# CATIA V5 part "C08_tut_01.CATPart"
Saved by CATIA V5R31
Part number: Part1
Bounding box of the stored display mesh (mm): x -175 to 175, y -250 to 250, z -8 to 100
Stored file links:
  D:\PROJECTS\Project 2021\US EDITION\CATIA V5 6R 2021\Resources\Tutorial Files\c08_catia_v5_6r2021_tut\C08_tut_01.CATPart
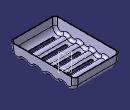
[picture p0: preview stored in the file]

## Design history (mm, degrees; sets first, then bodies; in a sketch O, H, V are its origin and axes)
Body1 (main body)
  Sketch1 on yz-plane, origin (0, 0, 0), H (0, 1, 0), V (0, 0, 1)
    point P1 (-250, 0)
    line L1 (-250, 0) -> (250, 0)
    line L2 (250, 0) -> (250, 100)
    line L3 (250, 100) -> (-250, 100)
    line L4 (-250, 100) -> (-250, 0)
    length L3 = 500
    length L2 = 100
    distance V L2 = 250
    coincidence: P1 H
    horizontal: L1 H, L3 H
    vertical: L2 V, L4 V
  Pad1: profile Sketch1, direction (1, 0, 0), length 175, mirrored extent
  Draft1: Angle -5, Neutral face of Pad1 from Sketch1.L3, PullDir face of Pad1 from Sketch1.L3
  Sketch2 on yz-plane, origin (0, 0, 0), H (0, 1, 0), V (0, 0, 1)
    arc A1 centre (-195.4346, 50) radius 50 from (-245.2443, 45.6422) to (-162.8621, 12.0654) ccw
    reference projected line E1 (-241.2511, 0) -> (-250, 100) from edge [end face of Pad1 | face of Pad1 from Sketch1.L4]
    reference projected line E2 (241.2511, 0) -> (-241.2511, 0) from edge [end face of Pad1 | face of Pad1 from Sketch1.L1]
    arc A2 centre (195.4346, 50) radius 50 from (162.8622, 12.0653) to (245.2443, 45.6422) ccw
    reference projected line E3 (250, 100) -> (241.2511, 0) from edge [end face of Pad1 | face of Pad1 from Sketch1.L2]
    reference projected line E4 (241.2511, 0) -> (-241.2511, 0) from edge [end face of Pad1 | face of Pad1 from Sketch1.L1]
    point P3 (97.7173, 50)
    point P4 (0, 50)
    point P5 (-97.7173, 50)
    construction line L1 (195.4346, 50) -> (-195.4346, 50)
    point P7 (-48.8586, -6.902)
    projected line E5 (250, 100) -> (241.2511, 0) from edge [end face of Pad1 | face of Pad1 from Sketch1.L2]
    projected line E6 (-241.2511, 0) -> (-250, 100) from edge [end face of Pad1 | face of Pad1 from Sketch1.L4]
    arc A3 centre (97.7173, 50) radius 50 from (65.1449, 12.0653) to (130.2898, 12.0654) ccw
    arc A4 centre (0, 50) radius 50 from (-32.5724, 12.0653) to (32.5725, 12.0654) ccw
    arc A5 centre (-97.7173, 50) radius 50 from (-130.2897, 12.0653) to (-65.1448, 12.0654) ccw
    point P23 (-245.2443, 45.6422)
    arc A6 centre (-146.5759, -6.902) radius 25 from (-130.2897, 12.0653) to (-162.8621, 12.0654) ccw
    arc A7 centre (-48.8586, -6.902) radius 25 from (-32.5724, 12.0653) to (-65.1448, 12.0654) ccw
    arc A8 centre (48.8586, -6.902) radius 25 from (65.1449, 12.0653) to (32.5725, 12.0654) ccw
    arc A9 centre (146.5759, -6.902) radius 25 from (162.8622, 12.0653) to (130.2898, 12.0654) ccw
    axis line L2 (146.5759, -6.902) -> (-146.5759, -6.902)
    line L3 (245.2443, 45.6422) -> (237.7725, -39.761)
    line L4 (-245.2443, 45.6422) -> (-237.7725, -39.761)
    line L5 (-237.7725, -39.761) -> (237.7725, -39.761)
    radius A1 = 50
    radius A6 = 25
    radius A5 = 50
    radius A7 = 25
    radius A4 = 50
    radius A8 = 25
    radius A3 = 50
    radius A9 = 25
    tangency: A1 E1, A1 E2, A2 E3, A2 E4, A6 A5, A7 A5, A6 A1, A7 A4, A8 A4, A8 A3, A3 A9, A9 A2, L3 A2, L4 A1
    horizontal: L1 H, L2 H, L5 H
    coincidence: P3 L1, P4 L1, P5 L1, P4 V, E6 P23, L2 P7
  Pocket1: profile Sketch2, direction (-1, 0, 0), through (limit type 3), opposite side length 175
  Fillet1: radius 25, on edge [face of Pocket1 | end face of Pad1]; edge [start face of Pad1 | face of Pad1 from Sketch1.L2]
  Shell1: ExtOffset 0, Face face of Pad1 from Sketch1.L3, IntOffset 5
  Sketch3 on xy-plane, origin (0, 0, 0), H (1, 0, 0), V (0, 1, 0)
    point P1 (0, 195.4)
    line L1 (105, 183.4) -> (-105, 183.4)
    line L2 (-105, 207.4) -> (105, 207.4)
    arc A1 centre (105, 195.4) radius 12 from (105, 183.4) to (105, 207.4) ccw
    point P6 (105, 195.4)
    arc A2 centre (-105, 195.4) radius 12 from (-105, 207.4) to (-105, 183.4) ccw
    point P7 (-105, 195.4)
    point P8 (-105, 207.4)
    axis line L3 (105, 195.4) -> (-105, 195.4)
    reference projected line E1 (175, 250) -> (-175, 250) from edge [face of Pad1 from Sketch1.L2 | face of Pad1 from Sketch1.L3]
    distance P6 P7 = 210
    distance V P7 = 105
    distance L2 L1 = 24
    distance E1 L3 = 54.6
    coincidence: P1 V, A2 P8
    horizontal: L1 H, L2 H, L3 H
    equidistance: L1 L2 P1
    tangency: A1 L1, A2 L2, A1 L2, L1 A2
  Pocket2: profile Sketch3, direction (0, 0, -1), through (limit type 6), opposite side length 25
  RectPattern1: of Pocket2, direction 1 instances 5, spacing 97.7, along edge [end face of Pad1 | face of Pad1 from Sketch1.L3] reversed
  Sketch4 on xy-plane, origin (0, 0, 0), H (1, 0, 0), V (0, 1, 0)
    circle A1 centre (-135, -196) radius 10
    point P1 (-135, -196)
    reference projected line E1 (-175, 250) -> (-175, -250) from edge [start face of Pad1 | face of Pad1 from Sketch1.L3]
    reference projected line E2 (-175, -250) -> (175, -250) from edge [face of Pad1 from Sketch1.L4 | face of Pad1 from Sketch1.L3]
    radius A1 = 10
    distance E1 P1 = 40
    distance P1 E2 = 54
  Pad2: profile Sketch4, direction (0, 0, 1), up to the existing solid (limit type 2), opposite side length 8
  RectPattern2: of Pad2, direction 1 instances 2, spacing 390.8, along edge [start face of Pad1 | face of Pad1 from Sketch1.L3] reversed, direction 2 instances 2, spacing 270, along edge [face of Pad1 from Sketch1.L4 | face of Pad1 from Sketch1.L3]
